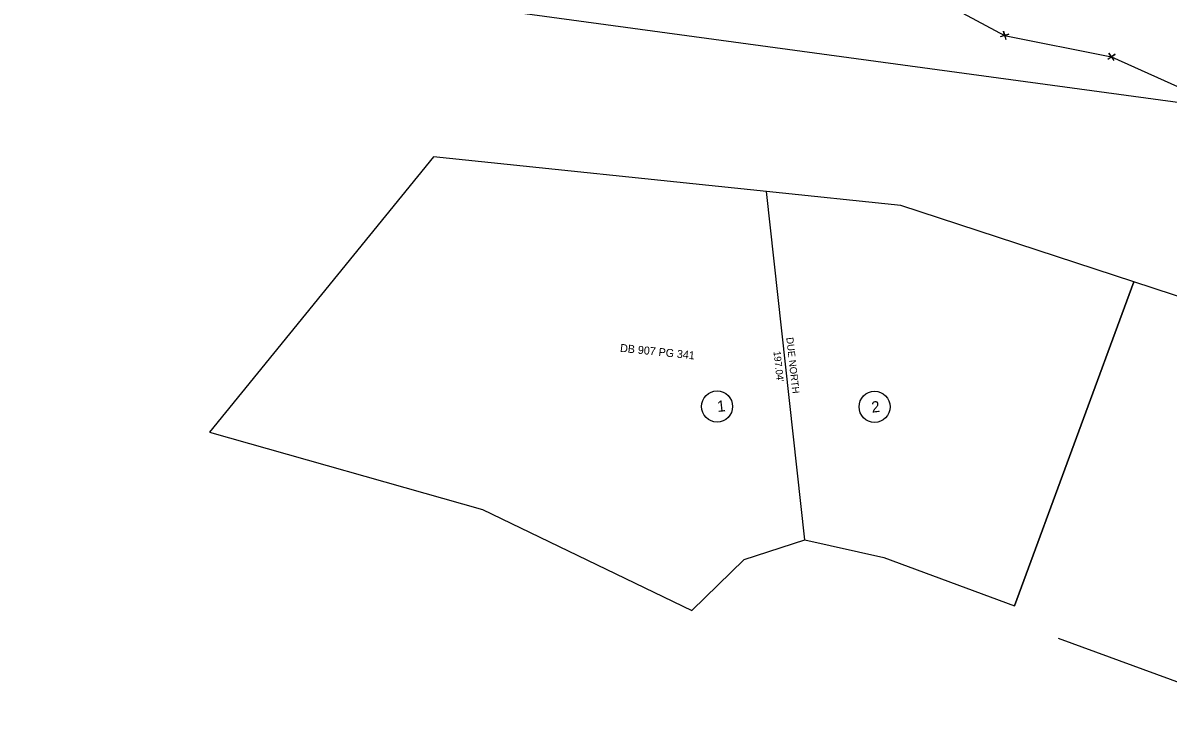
# Model space of a CAD drawing. Extents: x 2627243 to 2636458, y 566398 to 571062.
# Drawn here: x 2634753 to 2635397, y 568144 to 568538 of the extents above; entities that cross this region are included whole.
import ezdxf

# ---------------------------------------------------------------- set-up
doc = ezdxf.new("R2010")
doc.units = 0
for name, color, linetype in [('Exist Property Corner CELL', 7, 'Continuous'), ('Exist Property Line', 7, 'Continuous'), ('Scratch_Level_0', 7, 'Continuous'), ('Scratch_Level_2', 7, 'Continuous')]:
    doc.layers.add(name, color=color, linetype=linetype)

msp = doc.modelspace()

# ---------------------------------------------------------------- linework, layer by layer
at = {"layer": 'Exist Property Corner CELL'}
for p, q in [((2635305, 568531), (2635305, 568531)), ((2635365, 568519), (2635365, 568519))]:
    msp.add_line(p, q, dxfattribs=at)
for points in [[(2635302.6, 568530.28), (2635307.4, 568531.72), (2635305, 568531), (2635304.28, 568533.4), (2635305.72, 568528.6)], [(2635362.92, 568517.61), (2635367.08, 568520.39), (2635365, 568519), (2635363.61, 568521.08), (2635366.39, 568516.92)]]:
    msp.add_lwpolyline(points, dxfattribs=at)
at = {"layer": 'Exist Property Line'}
for p, q in [((2635255, 568558), (2635305, 568531)), ((2635305, 568531), (2635365, 568519)), ((2635365, 568519), (2635416, 568496))]:
    msp.add_line(p, q, dxfattribs=at)
at = {"layer": 'Scratch_Level_0'}
for p, q in [((2634984.03, 568462.72), (2634858, 568308)), ((2635171.14, 568443.28), (2634984.03, 568462.72)), ((2635192.77, 568247.43), (2635171.14, 568443.28)), ((2635246.61, 568435.43), (2635171.14, 568443.28)), ((2635377.61, 568392.5), (2635246.61, 568435.43)), ((2635310.48, 568210.37), (2635377.61, 568392.5)), ((2635377.61, 568392.5), (2635310.48, 568210.37)), ((2635482.85, 568358), (2635377.61, 568392.5)), ((2634858, 568308), (2635011.42, 568264.52)), ((2635011.42, 568264.52), (2635129.19, 568207.65)), ((2635158.51, 568236.31), (2635192.77, 568247.43)), ((2635192.64, 568247.36), (2635237.01, 568237.43)), ((2635129.19, 568207.65), (2635158.51, 568236.31)), ((2635237.01, 568237.43), (2635310.48, 568210.37)), ((2635335.1, 568192.2), (2635466.48, 568143.83))]:
    msp.add_line(p, q, dxfattribs=at)
for centre in [(2635143.34, 568322.37), (2635231.9, 568322.17)]:
    msp.add_circle(centre, 8.75, dxfattribs=at)
at = {"layer": 'Scratch_Level_2'}
msp.add_lwpolyline([(2633945.71, 569750.8), (2635590.54, 569527.29), (2635449.16, 568486.85), (2633804.33, 568710.36)], close=True, dxfattribs=at)

# ---------------------------------------------------------------- texts
at = {"layer": 'Scratch_Level_0'}
for s, height, rotation, p in [('DUE NORTH', 4, 276.30332, (2635182.23, 568361.06)), ('DB 907 PG 341', 4.5, 354.06814, (2635088.65, 568353.13)), ("197.04'", 4, 276.30332, (2635175.04, 568353.3)), ('1', 6.25, 6.30146, (2635143.69, 568319.26)), ('2', 6.25, 6.30146, (2635230.48, 568318.87))]:
    msp.add_text(s, height=height, rotation=rotation, dxfattribs=at).set_placement(p)

doc.saveas('drawing.dxf')
